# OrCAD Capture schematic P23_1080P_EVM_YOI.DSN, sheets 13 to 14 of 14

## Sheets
13 P13: Power Standalone Operation: size D
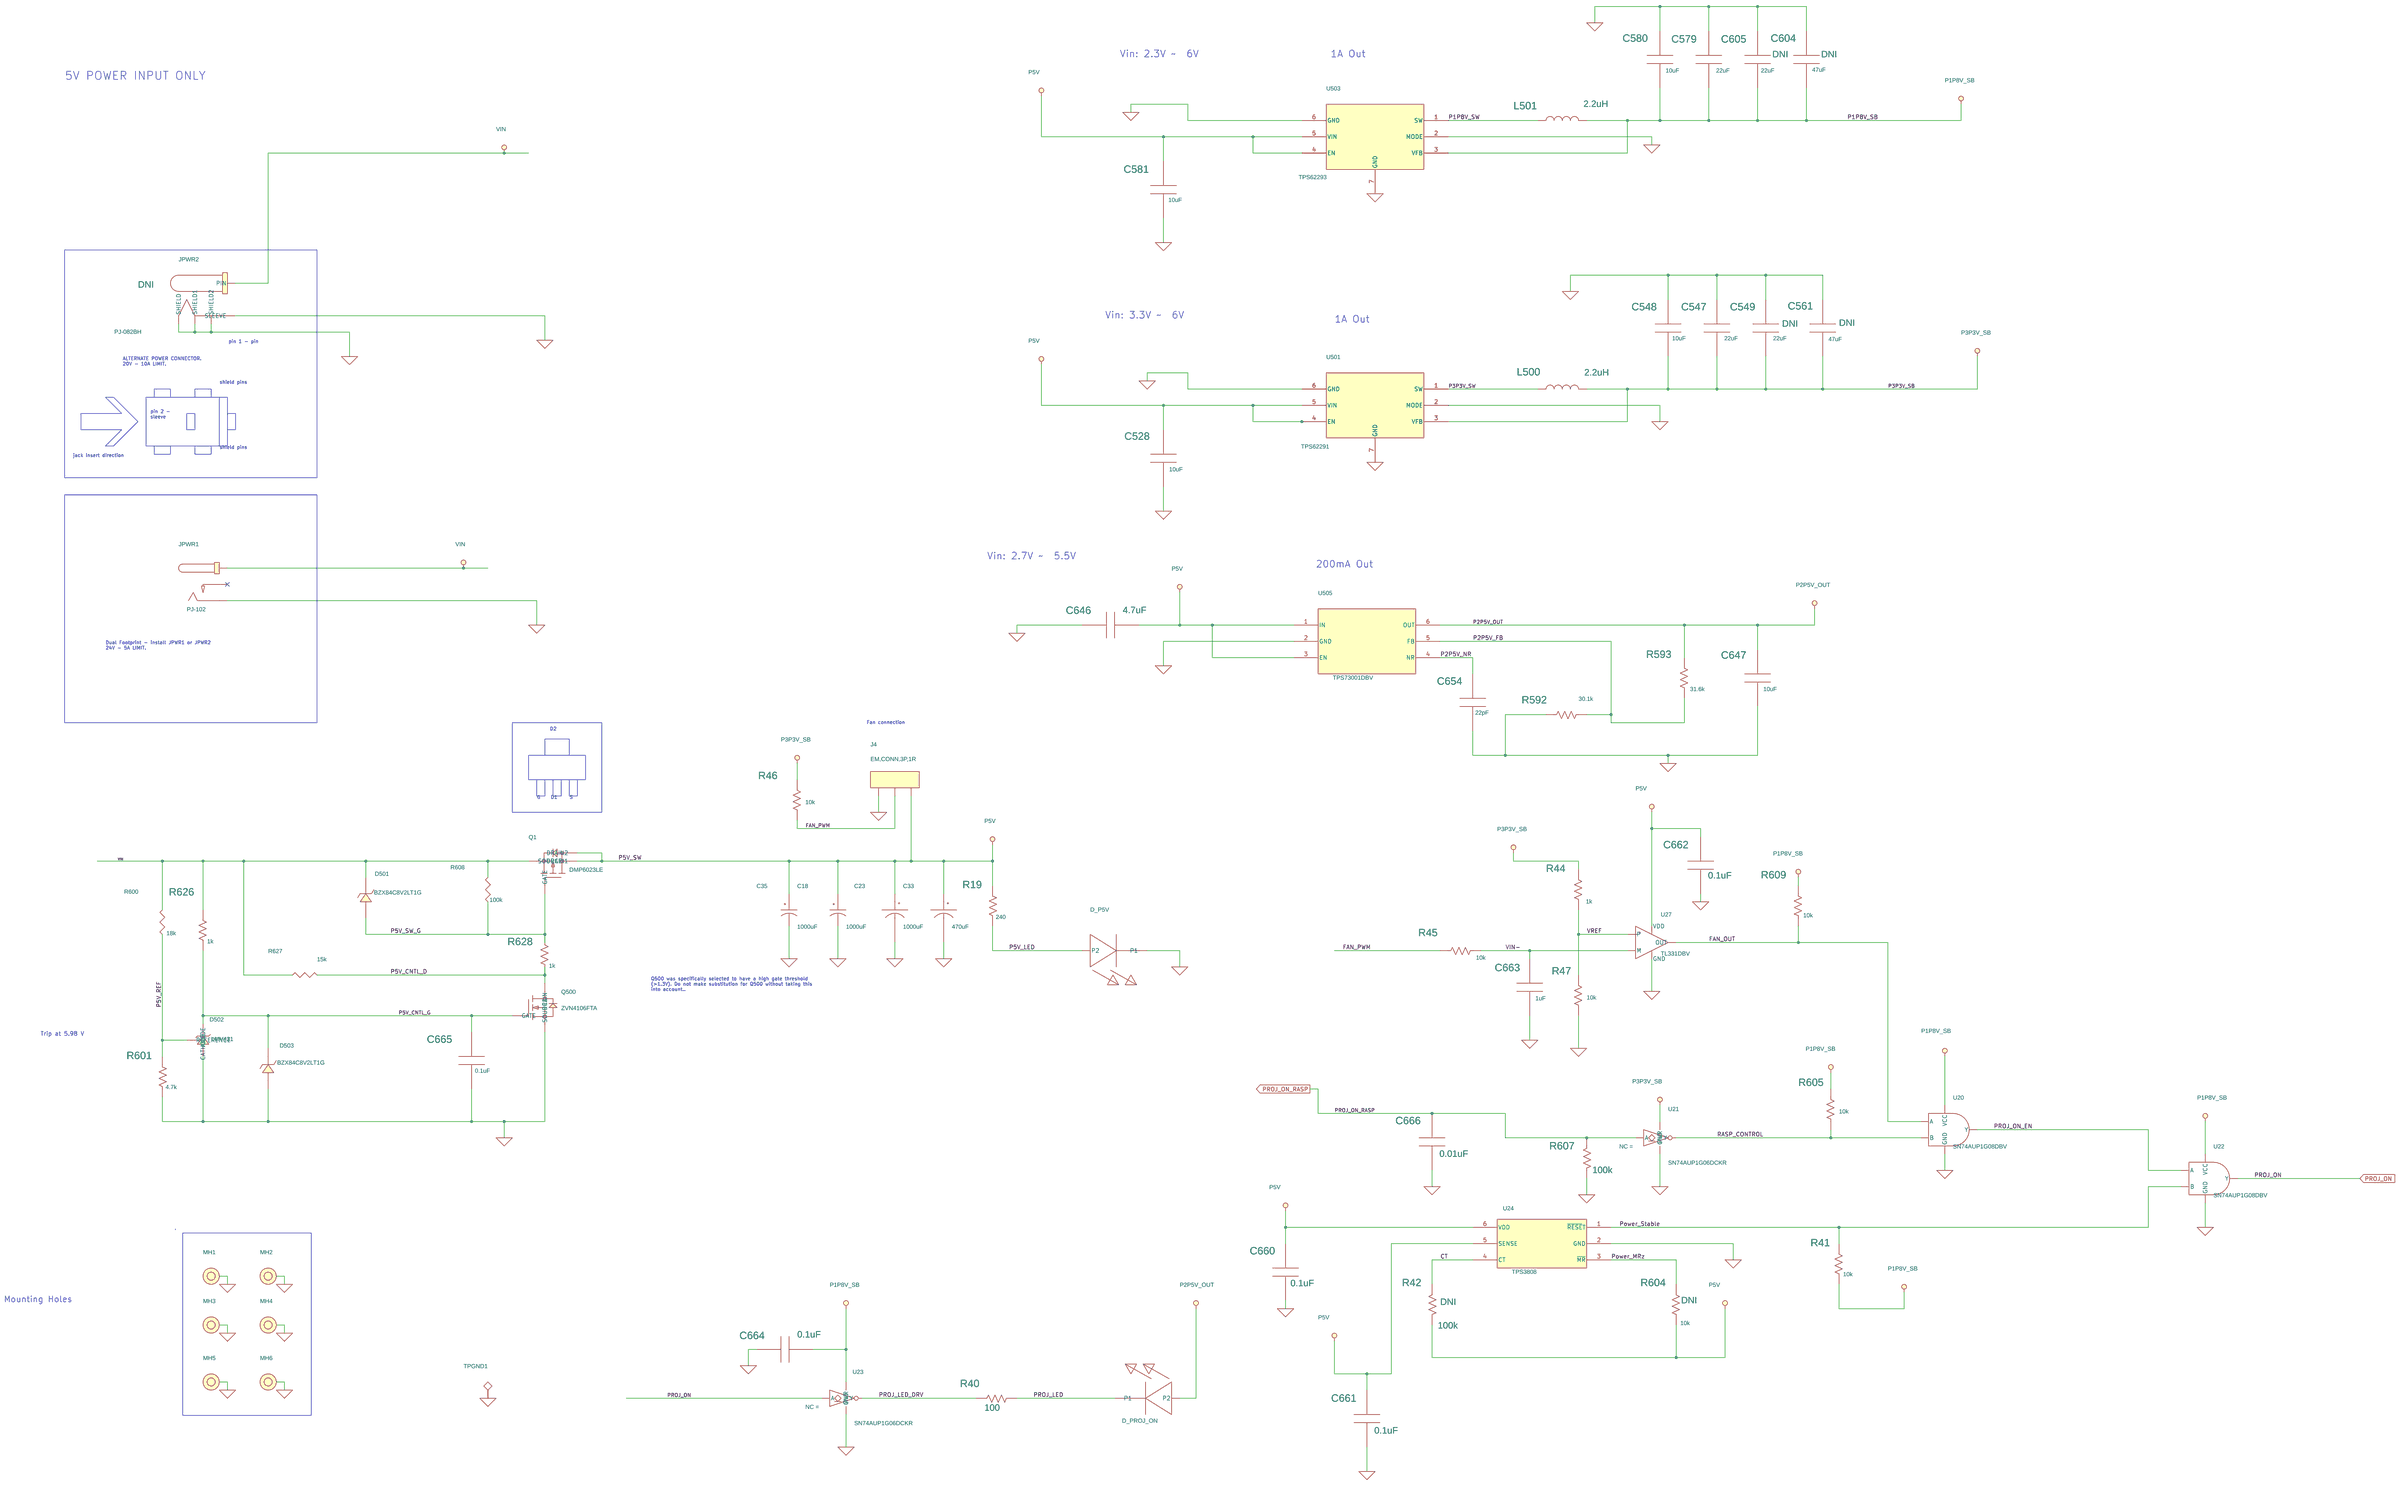
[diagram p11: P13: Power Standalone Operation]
14 P04: DMD Connection: size D
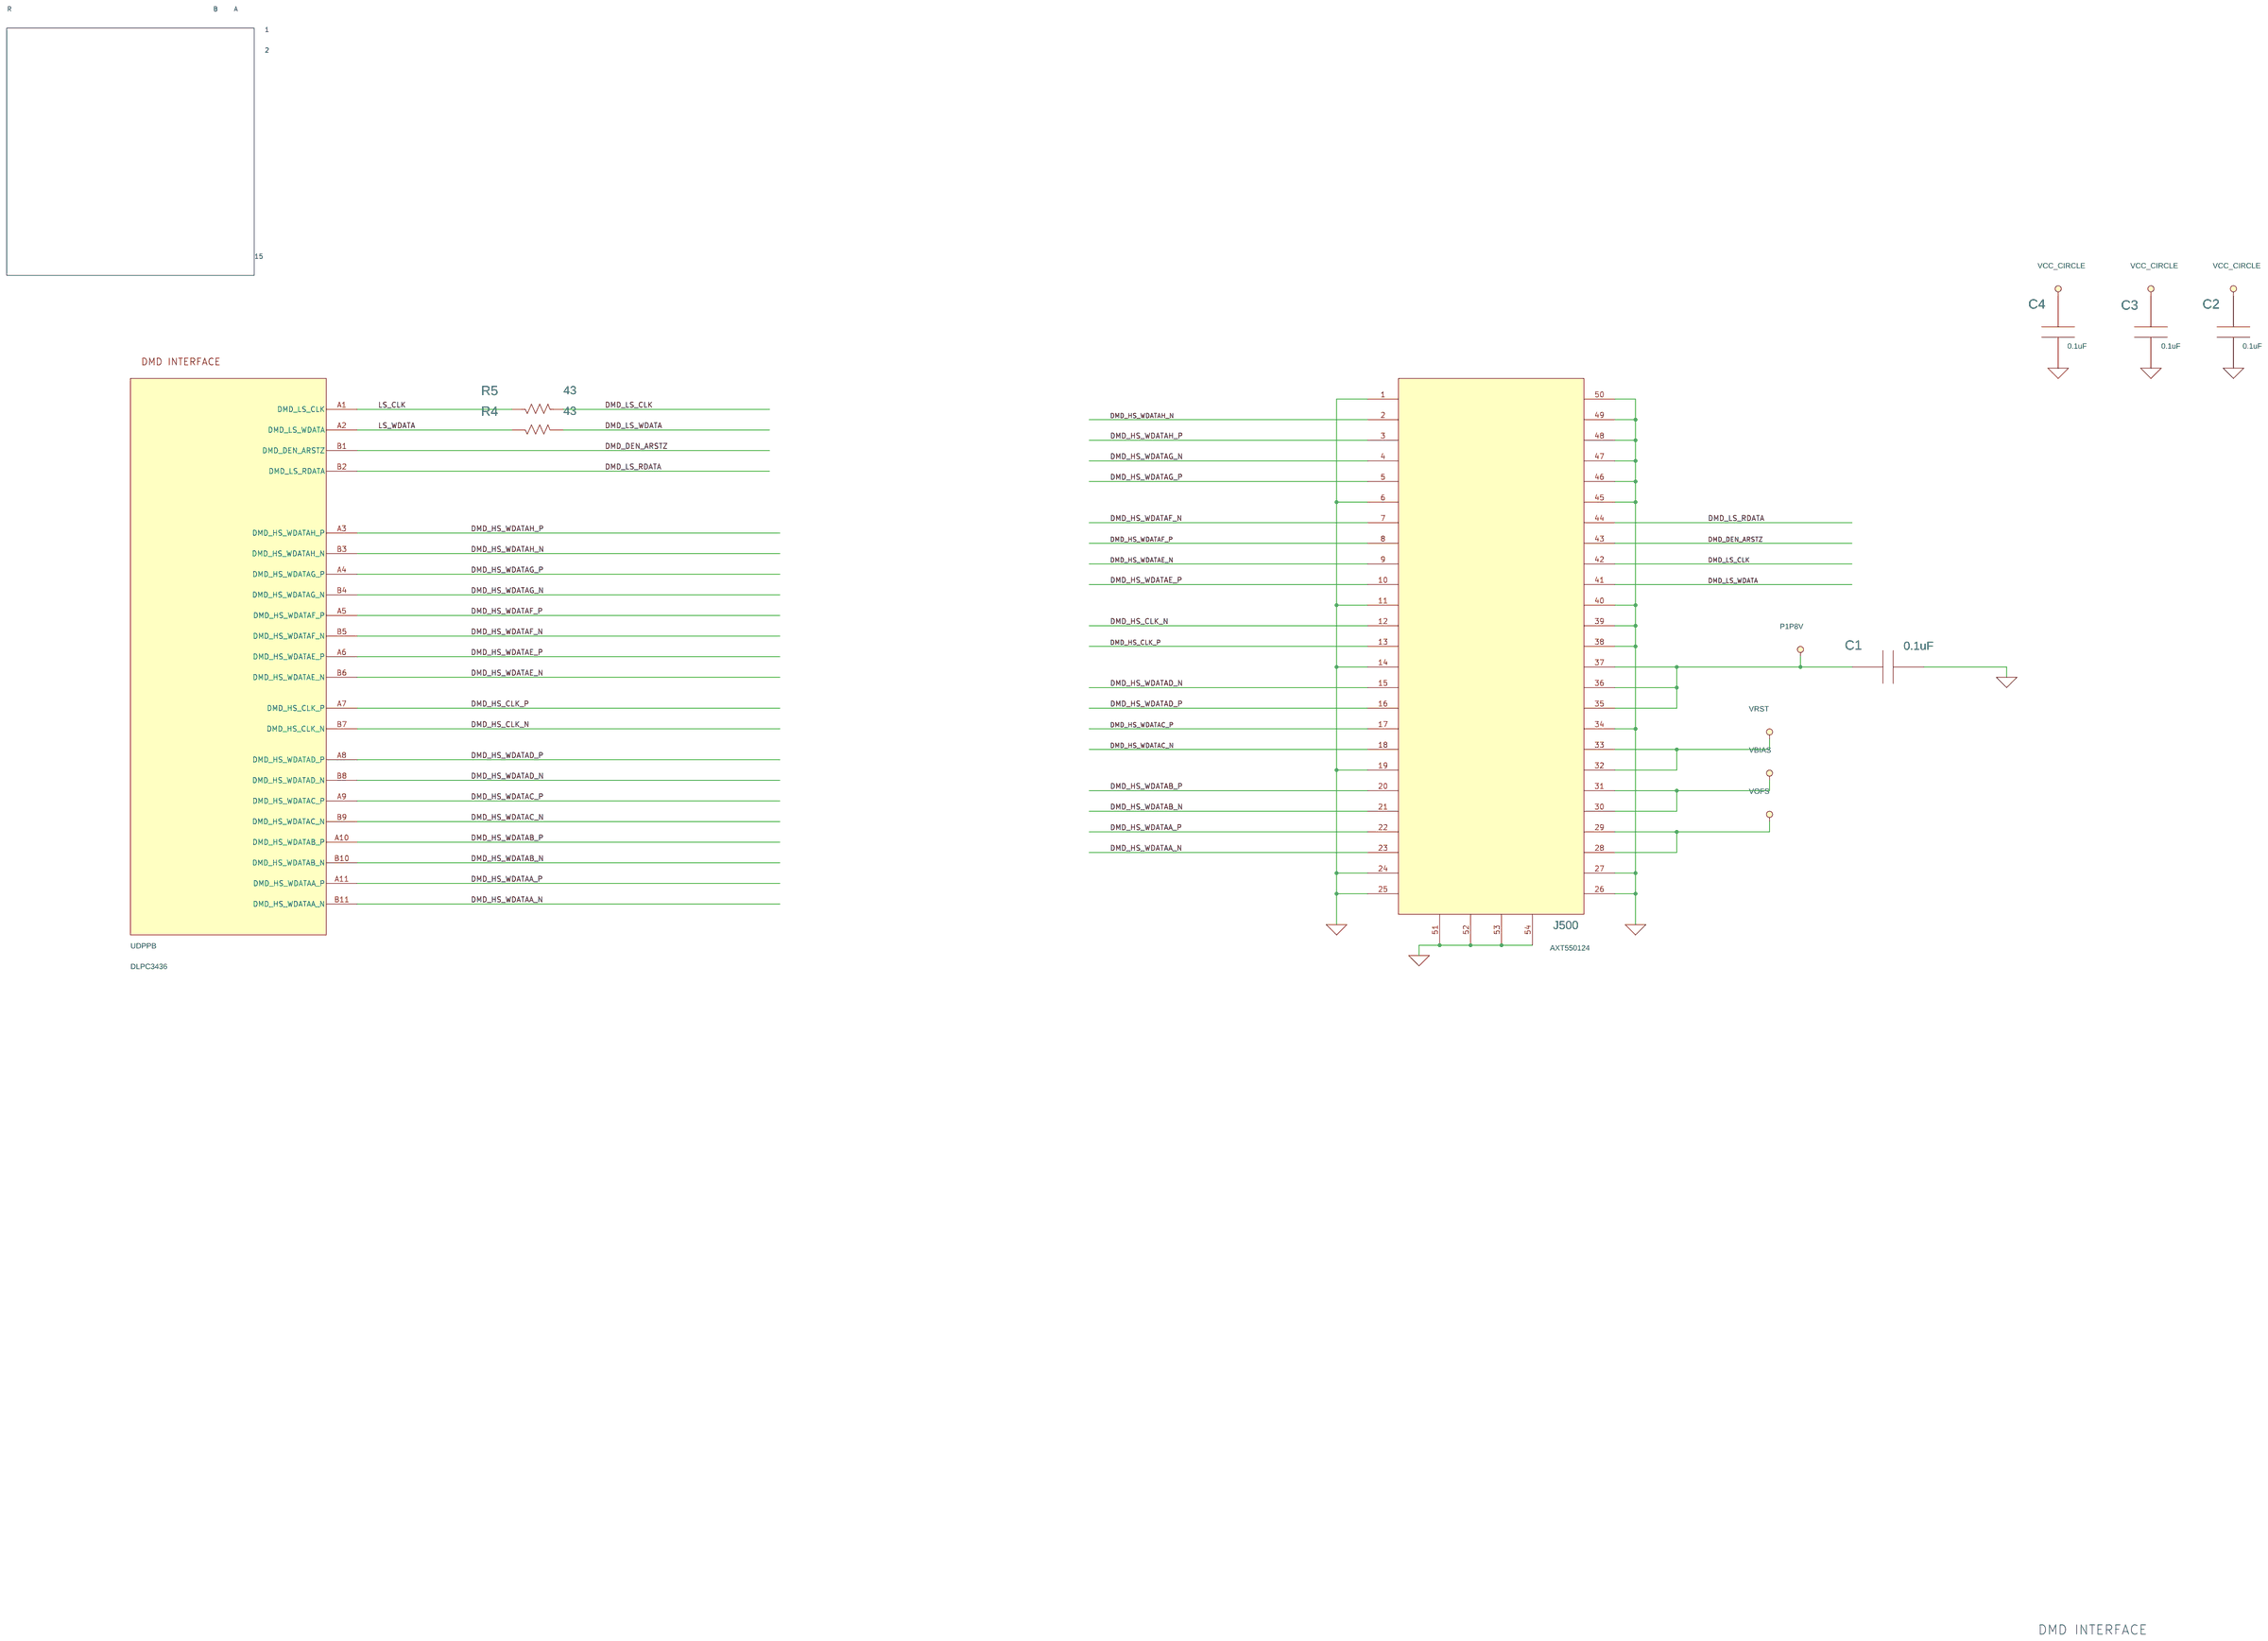
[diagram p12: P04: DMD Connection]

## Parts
sheet P04: DMD Connection
C1  0.1uF  [0402_AVXA]
C2  0.1uF  [0402]
C3  0.1uF  [0402]
C4  0.1uF  [0402]
J500  AXT550124  [Panasonic_AXT550124]
R4  43  [0201]
R5  43  [0201]
sheet P10: DLPA2005
UDPP  DLPC3436  [DPP3433_7mmx7mm_VFBGA_176balls]  (sections A,B,C,D,E,F,G,H)
sheet P13: Power Standalone Operation
C18  1000uF  [sizeF_327x327mil_radial_can]
C23  1000uF  [sizeF_327x327mil_radial_can]
C33  470uF  [sizeD_260x260mil_radial_can]
C35  1000uF  [sizeD_406x406mil_radial_can]
C528  10uF  [0603]
C547  22uF  [0603]
C548  10uF  [0603]
C549  22uF  [0603]
C561  47uF  [1206]
C579  22uF  [0603]
C580  10uF  [0603]
C581  10uF  [0603]
C604  47uF  [1206]
C605  22uF  [0603]
C646  4.7uF  [0402]
C647  10uF  [0603]
C654  22pF  [0402]
C660  0.1uF  [0402_AVXA]
C661  0.1uF  [0402_AVXA]
C662  0.1uF  [0402_AVXA]
C663  1uF  [0402]
C664  0.1uF  [0402_AVXA]
C665  0.1uF  [0402]
C666  0.01uF  [0402]
D501  BZX84C8V2LT1G  [ONSEMI_SOT23-3_CASE318_STYLE8]
D502  LMV431  [SOT23-3_DBZ003A]
D503  BZX84C8V2LT1G  [ONSEMI_SOT23-3_CASE318_STYLE8]
D_P5V  green  [1206]
D_PROJ_ON  green  [1206]
J4  EM,CONN,3P,1R  [JST_B3B_ZR]
JPWR1  PJ-102  [CUI_PJ-102BH]
JPWR2  PJ-082BH  [CUI_PJ-082BH]
L500  2.2uH  [1210]
L501  2.2uH  [1210]
MH1  -  [MH236-106]
MH2  -  [MH236-106]
MH3  -  [MH236-106]
MH4  -  [MH236-106]
MH5  -  [MH236-106]
MH6  -  [MH236-106]
Q1  DMP6023LE  [SOT223_DMP6023LE]
Q500  ZVN4106FTA  [SOT23-3_BSS138L]
R19  240  [0402]
R40  100  [0402]
R41  10k  [0402]
R42  100k  [0402]
R44  1k  [0402]
R45  10k  [0402]
R46  10k  [0402]
R47  10k  [0402]
R592  30.1k  [0402]
R593  31.6k  [0402]
R600  18k  [0402]
R601  4.7k  [0402]
R604  10k  [0402]
R605  10k  [0402]
R607  100k  [0402]
R608  100k  [0402]
R609  10k  [0402]
R626  1k  [0402]
R627  15k  [0402]
R628  1k  [0402]
TPGND1  TP_BLK  [KEYSTONE_TP_MINIATURE]
U20  SN74AUP1G08DBV  [SC70_DBV_R-PDSO-G5]
U21  SN74AUP1G06DCK  [U_5_DCK]
U22  SN74AUP1G08DBV  [SC70_DBV_R-PDSO-G5]
U23  SN74AUP1G06DCK  [U_5_DCK]
U24  TPS3808  [SOT23-6_DBV_R-PDSO-G6]
U27  TL331DBV  [SOT-23-5]
U501  TPS62291  [6-WDFN_Eposed_Pad]
U503  TPS62293  [6-WDFN_Eposed_Pad]
U505  TPS73001DBV  [SOT23-6_DBV_R-PDSO-G6]

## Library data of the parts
C1 = PAS,CAP,NP,large_2: DigiKey: 490-7998-1-ND; DigiReel: 490-7998-6-ND; Family: passive; Lead Style: SMT; MFG: Murata; Material: x7r; P/D_NUM: GCM155R71C104KA55J; Part Number: GCM155R71C104KA55J; Part Specific: CAP CER .1UF 16V X7R 0402; TOLERANCE: 10%; Type: capacitor; VENDOR: Murata; VPC: 16V
C2-C4 C665 = PAS,CAP,NP,large_2: DigiKey: 445-6899-1-ND; DigiReel: 445-6899-6-ND; Family: passive; Lead Style: SMT; MFG: TDK; Material: X7R; P/D_NUM: CGA2B3X7R1H104K050BB; Part Number: CGA2B3X7R1H104K050BB; Part Specific: 0.10µF 50V Ceramic Capacitor X7R 0402; TOLERANCE: 10%; Type: capacitor; VENDOR: TDK; VPC: 50V
J500 = EM,CONN,50P,2R,CNTR_CW_PINOUT_1: DigiKey: 255-2408-1-ND; DigiReel: 255-2408-6-ND; Family: electro/mechanical; Lead Style: SMT; MFG: Panasonic; Part Specific: CONN SOCKET F4S .4MM 50POS SMD; Pin Cnt: 50; Pin Spacing: 0.4mm; Row Cnt: 2; Type: connector; Vendor: Panasonic
R4 R5 = PAS,R,large: DigiKey: P43AGCT-ND; DigiReel: P43AGDKR-ND; Family: passive; Index PN: 1167; Lead Style: SMT; MFG: Panasonic; P/D_NUM: ERJ-1GEJ430C; Part Number: ERJ-1GEJ430C; Part Specific: RES 43 OHM 1/20W 5% 0201 SMD; TOLERANCE: 5%; Type: resistor; VENDOR: Panasonic; VPC: 1/20W
UDPP = TIDLP,DPP3430,_no_DSI: DigiKey: ---; DigiReel: ---; Family: processor; Lead Style: SMT; MFG: Texas Instruments; Mouser: ---; P/D_NUM: DLPC3436CZVBR; Part Number: DLPC3436CZVBR; Part Specific: DLP-PICO Processor; Type: dlp; Vendor: Texas Instruments; Install: Y
C18 = CAP_POL: Capacitor; DigiKey: P15081CT-ND; DigiReel: P15081TR-ND; Family: passive; Install: Y; Lead Style: SMT; MFG: Panasonic; Material: aluminum; P/D_NUM: EEE-FT1A102AP; Part Number: EEE-FT1A102AP; Part Specific: CAP ALUM 1000UF 20% 10V SMD; TOLERANCE: 20%; Type: capacitor; VPC: 10V; Vendor: Panasonic
C23 = PAS,CAP,POLARIZED,large: Capacitor; DigiKey: P15081CT-ND; DigiReel: P15081TR-ND; Lead Style: SMT; MFG: Panasonic; Material: aluminum; P/D_NUM: EEE-FT1A102AP; Part Number: EEE-FT1A102AP; Part Specific: CAP ALUM 1000UF 20% 10V SMD; Tolerance: 20%; VPC: 10V; Vendor: Panasonic
C33 = PAS,CAP,POLARIZED,large: Capacitor; DigiKey: PCE5009CT-ND; DigiReel: PCE5009DKR-ND; Lead Style: SMT; MFG: Panasonic; Material: aluminum; P/D_NUM: EEE-FTA471XAP; Part Number: EEE-FTA471XAP; Part Specific: CAP ALUM 470UF 20% 10V SMD; Tolerance: 20%; VPC: 10V; Vendor: Panasonic
C35 = CAP_POL: Capacitor; DigiKey: PCE3990CT-ND; DigiReel: PCE3990CT-ND; Family: passive; Install: Y; Lead Style: SMT; MFG: Panasonic; Material: aluminum; P/D_NUM: EEE-FC1A102P; Part Number: EEE-FC1A102P; Part Specific: CAP ALUM 1000UF 20% 10V SMD; TOLERANCE: 20%; Type: capacitor; VPC: 10V; Vendor: Panasonic
C528 C548 C580 = PAS,CAP,NP,large_2: DigiKey: 445-6853-1-ND; DigiReel: 445-6853-6-ND; Family: passive; Index PN: 1207; Lead Style: SMT; MFG: TDK; P/D_NUM: C1608X5R1A106M080AC; Part Number: C1608X5R1A106M080AC; Part Specific: CAP CER 10UF 10V 20% X5R 0603; TOLERANCE: 20%; Type: capacitor; VENDOR: TDK; VPC: 10V; Voltage: 6.3V
C547 C579 = PAS,CAP,NP,large: DigiKey: 445-9077-1-ND; DigiReel: 445-9077-6-ND; Family: passive; Index PN: 1203; Lead Style: SMT; MFG: TDK; Material: x5r; P/D_NUM: C1608X5R1A226M080AC; Part Number: C1608X5R1A226M080AC; Part Specific: CAP CER 22UF 10V 20% X5R 0603; TOLERANCE: 20%; Type: capacitor; VENDOR: TDK; VPC: 10V
C549 C605 = PAS,CAP,NP,large: DigiKey: 445-9077-1-ND; DigiReel: 445-9077-6-ND; Family: passive; Index PN: 1203; Install: DNI; Lead Style: SMT; MFG: TDK; Material: x5r; P/D_NUM: C1608X5R1A226M080AC; Part Number: C1608X5R1A226M080AC; Part Specific: CAP CER 22UF 10V 20% X5R 0603; TOLERANCE: 20%; Type: capacitor; VENDOR: TDK; VPC: 10V
C561 C604 = PAS,CAP,NP,large: DigiKey: 490-5528-1-ND; DigiReel: 490-5528-6-ND; Family: passive; Install: DNI; Lead Style: SMT; MFG: Murata Electronics; Material: x5r; P/D_NUM: GRM31CR61A476ME15L; Part Number: GRM31CR61A476ME15L; Part Specific: CAP CER 47UF 10V X5R 1206; TOLERANCE: 20%; Type: capacitor; VENDOR: Murata; VPC: 10V
C581 = PAS,CAP,NP,large_2: DigiKey: 445-6853-1-ND; DigiReel: 445-6853-6-ND; Family: passive; Index PN: 1207; Lead Style: SMT; MFG: TDK; P/D_NUM: C1608X5R1A106M080AC; Part Number: C1608X5R1A106M080AC; Part Specific: CAP CER 10UF 10V 20% X5R 0603; TOLERANCE: 20%; Type: capacitor; VENDOR: TDK; VPC: 10V; Voltage: 10V
C646 = PAS,CAP,NP,large: DigiKey: 445-7395-1-ND; DigiReel: 445-7395-6-ND; Family: passive; Lead Style: SMT; MFG: TDK; Material: x5r; P/D_NUM: C1005X5R0J475M050BC; Part Number: C1005X5R0J475M050BC; Part Specific: CAP CER 4.7UF 6.3V 20% X5R 0402; TOLERANCE: 20%; Type: capacitor; VENDOR: TDK; VPC: 6.3V
C647 = PAS,CAP,NP,large: DigiKey: 445-4112-1-ND; DigiReel: 445-4112-6-ND; Family: passive; Index PN: 906; Lead Style: SMT; MFG: TDK; Material: x5r; P/D_NUM: C1608X5R0J106M080AB; Part Number: C1608X5R0J106M080AB; Part Specific: CAP CERAMIC 10UF 6.3V X5R 0603; TOLERANCE: 20%; Type: capacitor; VENDOR: TDK; VPC: 6.3V
C654 = PAS,CAP,NP,large: DigiKey: 490-17747-1-ND; DigiReel: 490-17747-6-ND; Family: passive; Lead Style: SMT; MFG: Murata; Material: npo; P/D_NUM: GCM1555C1H220JA16J; Part Number: GCM1555C1H220JA16J; Part Specific: CAP CER 22PF 50V NP0 0402; TOLERANCE: 5%; Type: capacitor; VENDOR: Murata; VPC: 50V
C660-C662 C664 = PAS,CAP,NP,large: DigiKey: 490-7998-1-ND; DigiReel: 490-7998-6-ND; Family: passive; Lead Style: SMT; MFG: Murata; Material: x7r; P/D_NUM: GCM155R71C104KA55J; Part Number: GCM155R71C104KA55J; Part Specific: CAP CER .1UF 16V X7R 0402; TOLERANCE: 10%; Type: capacitor; VENDOR: Murata; VPC: 16V
C663 = PAS,CAP,NP,large_2: DigiKey: 587-3245-1-ND; DigiReel: 587-3245-6-ND; Family: passive; Lead Style: SMT; MFG: Taiyo Yuden; Material: x5r; P/D_NUM: TMK105BJ105MV-F; Part Number: TMK105BJ105MV-F; Part Specific: CAP CER 1.0UF 25V X5R 0402; TOLERANCE: 20%; Type: capacitor; VENDOR: Taiyo Yuden; VPC: 25V; Voltage: 25V
C666 = PAS,CAP,NP,large: DigiKey: 399-1038-1-ND; DigiReel: 399-1038-6-ND; Family: passive; Lead Style: SMT; MFG: KEMET; Material: x7r; P/D_NUM: C0402C103K4RACTU; Part Number: C0402C103K4RACTU; Part Specific: CAP CER 10000PF 16V X7R 0402; TOLERANCE: 10%; Type: capacitor; VENDOR: KEMET; VPC: 16V
D501 = PAS,DIODE,ZENOR,SOT-23,Ap1,Cp3: DigiKey: BZX84C8V2LT1GOSCT-ND; DigiReel: BZX84C8V2LT1GOSDKR-ND; Index PN: 1396; Install: Y; MFG: ON Semiconductor; Part Specific: DIODE ZENER 8.2V 225MW SOT23-3; Type: diode,zener; VPC: 8.2V; Vendor: ON Semiconductor
D502 = PWR,REF,LMV431A,SOT-23: DigiKey: LMV431AIMFX/NOPBCT-ND; DigiReel: LMV431AIMF/NOPBDKR-ND; Digikey Part Number: LMV431AIMFX/NOPBCT-ND; Family: power; Index PN: 1533; Install: Y; Lead Style: SMT; MFG: Texas Instruments; P/D_NUM: LMV431AIMFX/NOPB; Part Number: LMV431AIMFX/NOPB; Part Specific: IC VREF SHUNT ADJ SOT23-3; Type: shunt; Vendor: Texas Instruments
D503 = PAS,DIODE,ZENOR,SOT-23,Ap1,Cp3: DigiKey: BZX84C8V2LT1GOSCT-ND; DigiReel: BZX84C8V2LT1GOSDKR-ND; Digikey Part Number: BZX84C8V2LT1GOSCT-ND; Index PN: 1396; Install: Y; MFG: ON Semiconductor; Part Specific: DIODE ZENER 8.2V 225MW SOT23-3; Type: diode,zener; VPC: 8.2V; Vendor: ON Semiconductor
D_P5V D_PROJ_ON = PAS,DIODE,LED,large: DigiKey: 67-1357-1-ND; DigiReel: 67-1357-6-ND; Family: passive; Index PN: 31; Install: Y; Lead Style: SMT; MFG: Lumex; P/D_NUM: SML-LX1206GC-TR; Part Number: SML-LX1206GC-TR; Part Specific: LED 565NM WTR CLR GREEN 1206 SMD; Type: diode,led; VENDOR: Lumex
J4 = EM,CONN,3P,1R: DigiKey: 455-1658-ND; DigiReel: ---; Install: Y; MFG: JST Sales America Inc.; P/D_NUM: B3B-ZR(LF)(SN); Part Number: B3B-ZR(LF)(SN); Part Specific: CONN HEADER VERT 3POS 1.5MM; Pin Cnt: 3; Pin Spacing: 1.5mm; VENDOR: JST Sales America Inc.
JPWR1 = EM,CONN,PWRJACK,PJ1-022_0: DigiKey: CP-102BH-ND; DigiReel: ---; Install: Y; MFG: CUI Inc; P/D_NUM: PJ-102BH; Part Number: PJ-102BH; Part Specific: CONN PWR JACK 2.5X5.5MM SOLDER; Type: connector; VENDOR: CUI Inc
JPWR2 = EM,CONN,PWRJACK,PJ-082BH_1: DigiKey: CP-082BHCT-ND; DigiReel: ---; Family: electro/mechanical; Index PN: 1369; Install: DNI; Lead Style: TH; MFG: CUI Stack; Part Specific: CONN PWR JACK 2.5X5.5MM PCB 10A; Type: connector; VENDOR: CUI Stack
L500 L501 = PAS,INDUCTOR,_large: DigiKey: 490-16005-1-ND; DigiReel: 490-16005-6-ND; Family: passive; Install: Y; Lead Style: SMT; MFG: Murata; P/D_NUM: LQH32PH2R2NN0L; Part Number: LQH32PH2R2NN0L; Part Specific: FIXED IND 2.2UH 1.6A 91.2 MOHM; Type: inductor; VENDOR: Murata
MH1-MH6 = PL_MTG_0: Install: DNI; Manufacturer: -- NOT A PART --; Part Specific: Mounting Hole; Type: Mounting Hole; Vendor: -- NOT A PART --
Q1 = ANA,MOSFET,P-CH,E,SOT223: DigiKey: DMP6023LE-13DITR-ND; DigiReel: DMP6023LE-13DIDKR-ND; Digikey Part Number: DMP6023LE-13DITR-ND; Family: analog; Index PN: 1531; Lead Style: SMT; MFG: Diodes Incorporated; Part Specific: MOSFET P-CH 60V 7A SOT223; Type: fet; Vendor: Diodes Incorporated
Q500 = ANA,MOSFET,N-CH,E,2N7002,SOT-23: DigiKey: ZVN4106FCT-ND; DigiReel: ---; Family: analog; Index PN: 1587; Lead Style: SMT; MFG: Diodes Incorporated; Part Specific: MOSFET N-CH 60V 200MA SOT23-3; Type: fet; VPC: 60V; Vendor: Diodes Incorporated
R19 = PAS,R,large: DigiKey: P240LCT-ND; DigiReel: P240LDKR-ND; Family: passive; Index PN: 1303; Lead Style: SMT; MFG: Panasonic; P/D_NUM: ERJ-2RKF2400X; Part Number: ERJ-2RKF2400X; Part Specific: RES SMD 240 OHM 1% 1/10W 0402; TOLERANCE: 1%; Type: resistor; VENDOR: Panasonic; VPC: 1/16W
R40 = PAS,R,large: DigiKey: P100LCT-ND; DigiReel: P100LDKR-ND; Family: passive; Index PN: 690; Lead Style: SMT; MFG: Panasonic; Material: chip; P/D_NUM: ERJ-2RKF1000X; Part Number: ERJ-2RKF1000X; Part Specific: RES 100 OHM 1/10W 1% 0402 SMD; Power: 1/16W; TOLERANCE: 1%; Type: resistor; VENDOR: Panasonic; VPC: 1/16W
R41 R45-R47 R605 R609 = PAS,R,large: DigiKey: P10.0KLCT-ND; DigiReel: P10.0KLDKR-ND; Family: passive; Index PN: 680; Install: Y; Lead Style: SMT; MFG: Panasonic; Material: chip; P/D_NUM: ERJ-2RKF1002X; Part Number: ERJ-2RKF1002X; Part Specific: RES SMD 10K OHM 1% 1/10W 0402; Power: 1/16W; TOLERANCE: 1%; Type: resistor; VENDOR: Panasonic; VPC: 1/16W
R42 = PAS,R,large: DigiKey: 541-100KLCT-ND; DigiReel: 541-100KLDKR-ND; Family: passive; Index PN: 712; Install: DNI; Lead Style: SMT; MFG: Vishay/Dale; Material: chip; P/D_NUM: CRCW0402100KFKED; Part Number: CRCW0402100KFKED; Part Specific: RES 100K OHM 1/10W 1% 0402 SMD; Power: 1/16W; TOLERANCE: 1%; Type: resistor; VPC: 1/16W; Vendor: Vishay/Dale
R44 R626 R628 = PAS,R,large: DigiKey: P1.00KLCT-ND; DigiReel: P1.00KLDKR-ND; Family: passive; Index PN: 684; Install: Y; Lead Style: SMT; MFG: Panasonic; Material: chip; P/D_NUM: ERJ-2RKF1001X; Part Number: ERJ-2RKF1001X; Part Specific: RES 1.00K OHM 1/10W 1% 0402 SMD; Power: 1/16W; TOLERANCE: 1%; Type: resistor; VENDOR: Panasonic; VPC: 1/16W
R592 = PAS,R,large: DigiKey: P30.1KLCT-ND; DigiReel: P30.1KLDKR-ND; Family: passive; Index PN: 1335; Lead Style: SMT; MFG: Panasonic; P/D_NUM: ERJ-2RKF3012X; Part Number: ERJ-2RKF3012X; Part Specific: 30.1k Ohm ±1% 0.1W 1/10W Surface Mount Resistor Thick Film ±100ppm/°C 0402; TOLERANCE: 1%; Type: resistor; VENDOR: Panasonic; VPC: 1/16W
R593 = PAS,R,large: DigiKey: P31.6KLCT-ND; DigiReel: P31.6KLDKR-ND; Family: passive; Index PN: 1336; Lead Style: SMT; MFG: Panasonic; P/D_NUM: ERJ-2RKF3162X; Part Number: ERJ-2RKF3162X; Part Specific: 31.6k Ohm ±1% 0.1W 1/10W Surface Mount Resistor Thick Film ±100ppm/°C 0402; TOLERANCE: 1%; Type: resistor; VENDOR: Panasonic; VPC: 1/16W
R600 = PAS,R: DigiKey: 311-18.0KLRCT-ND; DigiReel: 311-18.0KLRTR-ND; Lead Style: SMT; MFG: Yageo; Material: chip; P/D_NUM: RC0402FR-0718KL; Part Number: RC0402FR-0718KL; Part Specific: RES SMD 18K OHM 1% 1/16W 0402; Tolerance: 1%; VPC: 1/16W; Vendor: Yageo
R601 = PAS,R,large: DigiKey: P4.70KLCT-ND; DigiReel: P4.70KLDKR-ND; Family: passive; Index PN: 1219; Lead Style: SMT; MFG: Panasonic; P/D_NUM: ERJ-2RKF4701X; Part Number: ERJ-2RKF4701X; Part Specific: RES 4.7K OHM 1/10W 1% 0402 SMD; Type: resistor; VENDOR: Panasonic; VPC: 1/16W
R604 = PAS,R,large: DigiKey: P10.0KLCT-ND; DigiReel: P10.0KLDKR-ND; Family: passive; Index PN: 680; Install: DNI; Lead Style: SMT; MFG: Panasonic; Material: chip; P/D_NUM: ERJ-2RKF1002X; Part Number: ERJ-2RKF1002X; Part Specific: RES SMD 10K OHM 1% 1/10W 0402; Power: 1/16W; TOLERANCE: 1%; Type: resistor; VENDOR: Panasonic; VPC: 1/16W
R607 = PAS,R,large: DigiKey: 541-100KLCT-ND; DigiReel: 541-100KLDKR-ND; Family: passive; Index PN: 712; Lead Style: SMT; MFG: Vishay/Dale; Material: chip; P/D_NUM: CRCW0402100KFKED; Part Number: CRCW0402100KFKED; Part Specific: RES 100K OHM 1/10W 1% 0402 SMD; Power: 1/16W; TOLERANCE: 1%; Type: resistor; VPC: 1/16W; Vendor: Vishay/Dale
R608 = PAS,R: DigiKey: 541-100KLCT-ND; DigiReel: 541-100KLDKR-ND; Index PN: 712; Lead Style: SMT; MFG: Vishay/Dale; Material: chip; P/D_NUM: CRCW0402100KFKED; Part Number: CRCW0402100KFKED; Part Specific: RES 100K OHM 1/10W 1% 0402 SMD; Tolerance: 1%; VPC: 1/16W; Vendor: Vishay/Dale
R627 = PAS,R: DigiKey: P15.0KLTR-ND; DigiReel: P15.0KLDKR-ND; Digikey Part Number: P15.0KLTR-ND; Index PN: 714; MFG: Panasonic; Material: chip; P/D_NUM: ERJ-2RKF1502X; Part Number: ERJ-2RKF1502X; Part Specific: RES SMD 15K OHM 1% 1/10W 0402; Tolerance: 1%; VPC: 1/16W; Vendor: Panasonic
TPGND1 = EM,TERM,TESTPOINT: DigiKey: 5001K-ND; DigiReel: ---; Family: electro/mechanical; Index PN: 946; Install: Y; Lead Style: TH; MFG: Keystone; P/D_NUM: 5001; Part Number: 5001; Part Specific: TEST POINT PC MINI .040inD BLACK; Type: terminal; Vendor: Keystone
U20 U22 = LOG,AND,Tiny_Logic: DigiKey: 296-19074-6-ND; DigiReel: 296-41491-6-ND; Index PN: 1378; Lead Style: SMT; MFG: Texas Instruments; P/D_NUM: SN74AUP1G08DBVR; Part Number: SN74AUP1G08DBVR; Part Specific: AND Gate IC 1 Channel SOT-23-5; Type: and; Vendor: Texas Instruments
U21 U23 = LOG,INV,OPENDRN,SN74AUP1G06DCK: DigiKey: 296-17562-1-ND; DigiReel: 296-17562-6-ND; Family: logic; Index PN: 1026; Lead Style: SMT; MFG: Texas Instruments; P/D_NUM: SN74AUP1G06DCKR; Part Number: SN74AUP1G06DCKR; Part Specific: IC INVERTER SINGLE 1INPUT SC705, open drain; Type: buffer
U24 = PWR,REG,TPS3808: DigiKey: 296-17196-1-ND; DigiReel: 296-17196-2-ND; Family: supervisor; Install: Y; MFG: Texas Instruments; P/D_NUM: TPS3808G50DBVR; Part Number: TPS3808G50DBVR; Part Specific: IC VOLT SUPERVISOR 5.0V SOT23-6; Type: supervisor; Vendor: Texas Instruments
U27 = ANA,COMP,TLV3491DBV_0: DigiKey: 296-10168-1-ND; DigiReel: 296-10168-2-ND; MFG: Texas Instruments; P/D_NUM: TL331IDBVR; Part Number: TL331IDBVR; Part Specific: IC DIFF COMP SINGLE SOT23-5; Type: Comparator; Vendor: Texas Instruments
U501 = PWR,REG,TPS56229x,SOT23_DDC: DigiKey: 296-41859-1-ND; DigiReel: 296-41859-6-ND; Family: power; P/D_NUM: TPS62291DRVR; Part Number: TPS62291DRVR; Part Specific: IC REG BUCK 3.3V 1A 6SON; Type: regulator; Vendor: Texas Instruments
U503 = PWR,REG,TPS56229x,SOT23_DDC: DigiKey: 296-23104-1-ND; DigiReel: 296-23104-6-ND; Family: power; P/D_NUM: TPS62293DRVR; Part Number: TPS62293DRVR; Part Specific: IC REG BUCK 1.8V 1A 6SON; Type: regulator; Vendor: Texas Instruments
U505 = PWR,REG,TPS73001: DigiKey: 296-27055-1-ND; DigiReel: 296-27055-6-ND; Family: power; Index PN: 1331; Lead Style: SMT; MFG: Texas Instruments; P/D_NUM: TPS73001DBVR; Part Number: TPS73001DBVR; Part Specific: IC REG LDO ADJ 0.2A SOT23-5; Type: regulator; Vendor: Texas Instruments

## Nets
GND: C1.2(N) C2.1(P) C3.1(P) C4.1(P) C18.2 C23.2(N) C33.2(N) C35.2 C528.2(N) C547.1(P) C548.1(P) C549.1(P) C561.1(P) C579.1(P) C580.1(P) C581.2(N) C604.1(P) C605.1(P) C646.1(P) C647.2(N) C654.2(N) C660.1(P) C661.1(P) C662.1(P) C663.2(N) C664.1(P) C665.1(P) C666.1(P) D502.3(ANODE) D503.1(ANODE) D_P5V.1(P1) J4.3 J500.1 J500.6 J500.11 J500.14 J500.19 J500.24 J500.25 J500.26 J500.27 J500.34 J500.38 J500.39 J500.40 J500.45 J500.46 J500.47 J500.48 J500.49 J500.50 J500.51 J500.52 J500.53 J500.54 JPWR1.2 JPWR2.2(SLEEVE) JPWR2.3(SHIELD) JPWR2.4(SHIELD1) JPWR2.5(SHIELD2) MH1.1 MH2.1 MH3.1 MH4.1 MH5.1 MH6.1 Q500.2(SOURCE) R47.1(N1) R592.2(N2) R601.2(N2) R607.1(N1) TPGND1.1(P1) U20.3(GND) U21.3(GND) U22.3(GND) U23.3(GND) U24.2(GND) U27.2(GND) U501.2(MODE) U501.6(GND) U501.7(GND) U503.2(MODE) U503.6(GND) U503.7(GND) U505.2(GND) ; also on sheet 1 2 4 6 7 8 9 10 11 12
P5V: C18.1 C23.1(P) C33.1(P) C35.1 C528.1(P) C581.1(P) C646.2(N) C660.2(N) C661.2(N) C662.2(N) J4.1 Q1.D1(DRAIN1) Q1.D2(DRAIN2) R19.1(N1) R42.1(N1) R604.1(N1) U24.5(SENSE) U24.6(VDD) U27.5(VDD) U501.4(EN) U501.5(VIN) U503.4(EN) U503.5(VIN) U505.1(IN) U505.3(EN) ; also on sheet 1 2
P5V_CNTL_D: Q500.3(DRAIN) R627.2 R628.1(N1)
P5V_CNTL_G: C665.2(N) D502.2(CATHODE) D503.3(CATHODE) Q500.1(GATE) R626.1(N1)
P5V_LED: D_P5V.2(P2) R19.2(N2)
P5V_REF: D502.1(REFERENCE) R600.1 R601.1(N1)
P5V_SW_G: D501.1(ANODE) Q1.G(GATE) R608.1 R628.2(N2)
VIN: D501.3(CATHODE) JPWR1.1 JPWR2.1(PIN) Q1.S(SOURCE) R600.2 R608.2 R626.2(N2) R627.1
VIN-: C663.1(P) R45.1(N1) U27.1(M)
CT: R42.2(N2) U24.4(CT)
DMD_DEN_ARSTZ: J500.43 UDPP.B1(DMD_DEN_ARSTZ)
DMD_HS_CLK_N: J500.12 UDPP.B7(DMD_HS_CLK_N)
DMD_HS_CLK_P: J500.13 UDPP.A7(DMD_HS_CLK_P)
DMD_HS_WDATAA_N: J500.23 UDPP.B11(DMD_HS_WDATAA_N)
DMD_HS_WDATAA_P: J500.22 UDPP.A11(DMD_HS_WDATAA_P)
DMD_HS_WDATAB_N: J500.21 UDPP.B10(DMD_HS_WDATAB_N)
DMD_HS_WDATAB_P: J500.20 UDPP.A10(DMD_HS_WDATAB_P)
DMD_HS_WDATAC_N: J500.18 UDPP.B9(DMD_HS_WDATAC_N)
DMD_HS_WDATAC_P: J500.17 UDPP.A9(DMD_HS_WDATAC_P)
DMD_HS_WDATAD_N: J500.15 UDPP.B8(DMD_HS_WDATAD_N)
DMD_HS_WDATAD_P: J500.16 UDPP.A8(DMD_HS_WDATAD_P)
DMD_HS_WDATAE_N: J500.9 UDPP.B6(DMD_HS_WDATAE_N)
DMD_HS_WDATAE_P: J500.10 UDPP.A6(DMD_HS_WDATAE_P)
DMD_HS_WDATAF_N: J500.7 UDPP.B5(DMD_HS_WDATAF_N)
DMD_HS_WDATAF_P: J500.8 UDPP.A5(DMD_HS_WDATAF_P)
DMD_HS_WDATAG_N: J500.4 UDPP.B4(DMD_HS_WDATAG_N)
DMD_HS_WDATAG_P: J500.5 UDPP.A4(DMD_HS_WDATAG_P)
DMD_HS_WDATAH_N: J500.2 UDPP.B3(DMD_HS_WDATAH_N)
DMD_HS_WDATAH_P: J500.3 UDPP.A3(DMD_HS_WDATAH_P)
DMD_LS_CLK: J500.42 R5.1(N1)
DMD_LS_RDATA: J500.44 UDPP.B2(DMD_LS_RDATA)
DMD_LS_WDATA: J500.41 R4.1(N1)
FAN_OUT: R609.1(N1) U20.1(A) U27.4(OUT)
FAN_PWM: J4.2 R45.2(N2) R46.1(N1)
LS_CLK: R5.2(N2) UDPP.A1(DMD_LS_CLK)
LS_WDATA: R4.2(N2) UDPP.A2(DMD_LS_WDATA)
P1P8V: C1.1(P) J500.35 J500.36 J500.37 ; also on sheet 1 4 6 12
P1P8V_SB: C579.2(N) C580.2(N) C604.2(N) C605.2(N) C664.2(N) L501.1 R41.1(N1) R605.2(N2) R609.2(N2) U20.5(VCC) U22.5(VCC) U23.5(PWR) U503.3(VFB) ; also on sheet 1 2 4 6 7 10 11
P1P8V_SW: L501.2 U503.1(SW)
P2P5V_FB: R592.1(N1) R593.1(N1) U505.5(FB)
P2P5V_NR: C654.1(P) U505.4(NR)
P2P5V_SB: C647.1(P) D_PROJ_ON.2(P2) R593.2(N2) U505.6(OUT) ; also on sheet 2
P3P3V_SB: C547.2(N) C548.2(N) C549.2(N) C561.2(N) L500.1 R44.2(N2) R46.2(N2) U21.5(PWR) U501.3(VFB) ; also on sheet 2 7 10
P3P3V_SW: L500.2 U501.1(SW)
Power_MRz: R604.2(N2) U24.3(~{MR})
Power_Stable: R41.2(N2) U22.2(B) U24.1(~{RESE}T)
PROJ_LED: D_PROJ_ON.1(P1) R40.1(N1)
PROJ_LED_DRV: R40.2(N2) U23.4(Y)
PROJ_ON: U22.4(Y) U23.2(A) ; also on sheet 1 2
PROJ_ON_EN: U20.4(Y) U22.1(A)
PROJ_ON_RASP: C666.2(N) R607.2(N2) U21.2(A) ; also on sheet 10
RASP_CONTROL: R605.1(N1) U20.2(B) U21.4(Y)
VBIAS: C3.2(N) J500.30 J500.31 ; also on sheet 1
VOFS: C4.2(N) J500.28 J500.29 ; also on sheet 1
VREF: R44.1(N1) R47.2(N2) U27.3(P)
VRST: C2.2(N) J500.32 J500.33 ; also on sheet 1

Not connected (* = marked no-connect by the designer): JPWR1 3*

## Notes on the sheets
sheet 13
- Vin: 2.3V ~  6V
- 1A Out
- 5V POWER INPUT ONLY
- Vin: 3.3V ~  6V
- 1A Out
- pin 1 - pin
- ALTERNATE POWER CONNECTOR.
  20V - 10A LIMIT.
- shield pins
- pin 2 -
  sleeve
- jack insert direction
- shield pins
- Vin: 2.7V ~  5.5V
- 200mA Out
- Dual Footprint - install JPWR1 or JPWR2
  24V - 5A LIMIT.
- Fan connection
- D2
- G
- D1
- S
- Q500 was specifically selected to have a high gate threshold
  (>1.3V). Do not make substitution for Q500 without taking this
  into account..
- Trip at 5.98 V
- Mounting Holes
sheet 14
- R
- B
- A
- 1
- 2
- 15
- DMD INTERFACE
